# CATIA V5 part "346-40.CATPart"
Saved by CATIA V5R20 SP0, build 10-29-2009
Part number: 346-40
Definition: NONE
Nomenclature: 346-40
Source: Unknown
Description: 346-40
Bounding box of the stored display mesh (mm): x 0 to 80, y -41.5 to 41.5, z -41.5 to 41.5
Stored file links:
  C:\Users\Utente\Desktop\IO LAVORO\3D X SITO CF\X SITO\3D files 346\346-40.CATPart
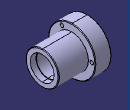
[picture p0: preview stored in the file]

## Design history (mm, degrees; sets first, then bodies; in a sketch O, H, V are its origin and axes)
Body1 "346-40" (main body)
  Solid1: solid without history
